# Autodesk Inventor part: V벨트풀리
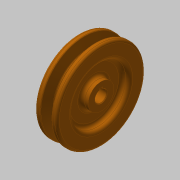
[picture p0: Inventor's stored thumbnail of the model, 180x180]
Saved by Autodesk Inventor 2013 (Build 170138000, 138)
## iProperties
Created: 2015-11
Part Number: V벨트풀리
Material: 알루미늄 6061
Document SubType Name: Modeling
Designer: mduedu
Density: 1 g/cm^3
Author: mduedu
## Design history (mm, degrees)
sketch "스케치1"
  geometry: L1 (-9.5, 0)-(9.5, 0); L2 (0, 0)-(0, 37.7); L3 (-4.825, 37.7)-(-9.5, 37.7); L4 (-9.5, 37.7)-(-9.5, 0); L5 (0, 28.7)-(-2.074, 28.7); L6 (-2.074, 28.7)-(-4.825, 37.7); L7 (4.825, 37.7)-(9.5, 37.7); L8 (9.5, 37.7)-(9.5, 0); L9 (0, 28.7)-(2.074, 28.7); L10 (2.074, 28.7)-(4.825, 37.7); L11 (-9.5, 35)-(9.5, 35); 3 further points
  constraints: 22 end point, 7 point on line, 4 perpendicular, 3 symmetric about line, 1 coincident, 1 horizontal, 1 horizontal alignment, 1 midpoint, 1 vertical
  dimensions: "d0" = 19 distance of L1.start L1.end; "d2" = 75.4 diameter of L2.end L1 (derived); "d3" = 34 deg angle of L10 L6; "d4" = 6.3 distance between parallel lines of L11 L9; "d5" = 2.7 distance between parallel lines of L7 L11; "d6" = 8 distance of point (4, 35) point (-4, 35); "d7" = 70 diameter of L11 L1
revolve "회전1" sketch "스케치1" stored, may be unused: angle "d8" = 90 deg
sketch "스케치2"
  geometry: C1 r 24 at (0, 0); C2 r 11 at (0, 0); 1 further point
  constraints: 2 centre point, 2 coincident
  dimensions: "d9" = 48 diameter of C1; "d10" = 22 diameter of C2
extrude "돌출1" cut sketch "스케치2" distance "d11" = 6; taper "d12" = 0 deg
fillet "모깎기1" dims "d13" = 3
fillet "모깎기2" dims "d14" = 3
fillet "모깎기3" dims "d15" = 1, "d16" = 0.5, "d17" = 2
hole "구멍1" diameter "d20" = 10; stored, may be unused: countersink angle "d24" = 90 deg, drill point angle "d26" = 118 deg; dims "d18" = 10, "d19" = 10, "d21" = 6, "d22" = 4, "d23" = 2, "d25" = 8
sketch "스케치3"
  geometry: L1 (-1.5, 0)-(1.5, 0); L2 (1.5, 0)-(1.5, 6.4); L3 (1.5, 6.4)-(-1.5, 6.4); L4 (-1.5, 6.4)-(-1.5, 0); 2 further points
  constraints: 8 end point, 2 parallel, 1 coincident, 1 horizontal, 1 midpoint, 1 perpendicular
  dimensions: "d27" = 3 distance of L2.end L3.end; "d29" = 6.4 distance of L3.end L1.start
extrude "돌출2" cut sketch "스케치3" stored distance "d30" = 6; taper "d31" = 0 deg
chamfer "모따기1" distance "d32" = 0.5; stored, may be unused: second distance "d33" = 2, angle "d34" = 45 deg
node "솔리드1"
mirror "대칭1"
